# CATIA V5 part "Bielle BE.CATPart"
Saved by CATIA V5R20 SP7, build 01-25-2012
Part number: Bielle BE
Publications: "Point.1", "Point.2", "Droite.2", "Droite.3"
Bounding box of the stored display mesh (mm): x -10 to 10, y 0 to 750, z 0 to 0
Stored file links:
  U:\IAO\IAO\IAO\Bielle BE.CATPart
  U:\IAO\IAO\IAO\Squelette.CATProduct
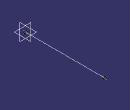
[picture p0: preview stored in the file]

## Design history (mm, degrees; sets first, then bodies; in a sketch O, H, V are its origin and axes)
External parameters (linked from other documents)
  `External.Longueur BC BE` = 750 mm
  `External.Longueur Demi Pivot` = 10 mm
Body1 (main body)
  Point1: (0, 0, 0)
  Line1: type Normal, RefPoint Point1, RefSkin zx-plane, Start 0, End 750 {= `External.Longueur BC BE`}
  Point2: (0, 0, 0), relative to vertex of Line1
  Line2: type PtDir, RefPoint Point1, Direction yz-plane, Start -10, End 10 {= `External.Longueur Demi Pivot`}
  Line3: type PtDir, RefPoint Point2, Direction yz-plane, Start -10, End 10 {= `External.Longueur Demi Pivot`}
